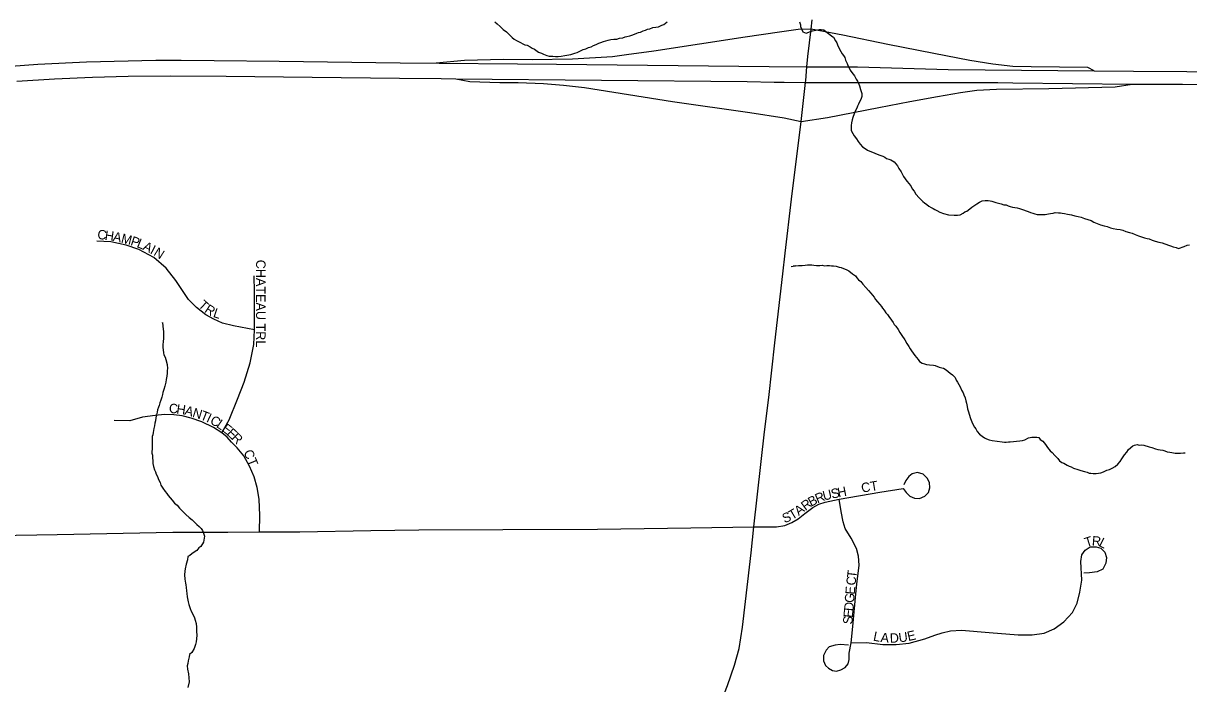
# Model space of a CAD drawing. Extents: x -10.1 to 68, y -9.5 to 29.2.
# Drawn here: x 4.36 to 5.531, y 18.755 to 19.418 of the extents above; entities that cross this region are included whole.
import ezdxf

# ---------------------------------------------------------------- set-up
doc = ezdxf.new("R2010")
doc.units = 0
for name, color, linetype in [('GM_X_Interchange_Ramps', 7, 'Continuous'), ('GM_X_Minor_River', 7, 'Continuous'), ('GM_X_Township_Road', 7, 'Continuous'), ('GM_X_Township_Subdivision', 7, 'Continuous'), ('GM_X_Township_Subdivision_Text', 7, 'Continuous'), ('GM_X_US_Route', 7, 'Continuous'), ('SH_Data', 7, 'Continuous')]:
    doc.layers.add(name, color=color, linetype=linetype)

msp = doc.modelspace()

# ---------------------------------------------------------------- linework, layer by layer
at = {"layer": 'GM_X_Interchange_Ramps'}
for points in [[(5.152, 19.4121), (5.1389, 19.4118), (5.1202, 19.4091), (5.0857, 19.4041), (4.9938, 19.3902), (4.9666, 19.3863), (4.9524, 19.3844), (4.9121, 19.3821), (4.8718, 19.3814), (4.8428, 19.3816), (4.8038, 19.3808), (4.7753, 19.3781)], [(5.4363, 19.3702), (5.4299, 19.3736), (5.3732, 19.3744), (5.3548, 19.3748), (5.3347, 19.3769), (5.3114, 19.3808), (5.2751, 19.3877), (5.2289, 19.3969), (5.1837, 19.4061), (5.152, 19.4121)], [(4.795, 19.3624), (4.8092, 19.3596), (4.8392, 19.3587), (4.8576, 19.3586), (4.8831, 19.3577), (4.9033, 19.3559), (4.9241, 19.3535), (4.9391, 19.3514), (5.0126, 19.3394), (5.0904, 19.3285), (5.1249, 19.3231), (5.1418, 19.3195)], [(5.1418, 19.3195), (5.1683, 19.3235), (5.2199, 19.3334), (5.251, 19.3395), (5.2791, 19.3447), (5.3019, 19.3487), (5.3183, 19.351), (5.3383, 19.3519), (5.3908, 19.3526), (5.4576, 19.3542), (5.4747, 19.3568)]]:
    msp.add_lwpolyline(points, dxfattribs=at)
at = {"layer": 'GM_X_Minor_River'}
for points in [[(4.8342, 19.4194), (4.8365, 19.4175), (4.8396, 19.415), (4.8427, 19.412), (4.8458, 19.4094), (4.8485, 19.4068), (4.8516, 19.4038), (4.8536, 19.4023), (4.8559, 19.4009), (4.8578, 19.3998), (4.8601, 19.3987), (4.8624, 19.3976), (4.8644, 19.3965), (4.8666, 19.3962), (4.8697, 19.3943), (4.8716, 19.3932), (4.874, 19.3921), (4.8782, 19.3892), (4.8809, 19.3881), (4.8832, 19.387), (4.8863, 19.3859), (4.8886, 19.3852), (4.8924, 19.3849), (4.895, 19.3846), (4.8977, 19.3847), (4.9007, 19.3851), (4.9045, 19.3856), (4.9106, 19.3869), (4.9125, 19.3873), (4.9144, 19.3881), (4.917, 19.3889), (4.9196, 19.3901), (4.923, 19.3917), (4.9257, 19.3925), (4.9283, 19.3937), (4.931, 19.3945), (4.9332, 19.3957), (4.9359, 19.3969), (4.9385, 19.3981), (4.9408, 19.3989), (4.9434, 19.3997), (4.9457, 19.4005), (4.9479, 19.401), (4.9506, 19.4018), (4.9536, 19.4022), (4.9567, 19.4023), (4.9593, 19.4031), (4.9627, 19.4036), (4.965, 19.4044), (4.9669, 19.4048), (4.9699, 19.4056), (4.9729, 19.4065), (4.9767, 19.4081), (4.9786, 19.4089), (4.9805, 19.4093), (4.9831, 19.4105), (4.9854, 19.4113), (4.9876, 19.4121), (4.9899, 19.4125), (4.9929, 19.4137), (4.996, 19.4142), (4.9986, 19.4146), (5.002, 19.4162), (5.0039, 19.417), (5.0073, 19.4194)], [(5.1404, 19.4196), (5.1412, 19.4166), (5.1413, 19.4147), (5.1425, 19.412), (5.1437, 19.4094), (5.1471, 19.4083), (5.1513, 19.4099), (5.1535, 19.4104), (5.16, 19.4117), (5.1619, 19.4117), (5.1646, 19.4114), (5.1669, 19.4099), (5.1707, 19.4069), (5.1727, 19.4051), (5.1746, 19.404), (5.1766, 19.4006), (5.1778, 19.3984), (5.1786, 19.3965), (5.1798, 19.3935), (5.1818, 19.3897), (5.1833, 19.3875), (5.1845, 19.3856), (5.1857, 19.3837), (5.1865, 19.3811), (5.1881, 19.3777), (5.1889, 19.3758), (5.1901, 19.3735), (5.1913, 19.3709), (5.1929, 19.3687), (5.1956, 19.3653), (5.1972, 19.3619), (5.1984, 19.36), (5.1999, 19.357), (5.2007, 19.3552), (5.2016, 19.3517), (5.2024, 19.3495), (5.2028, 19.3476), (5.2029, 19.3446), (5.2022, 19.3426), (5.1996, 19.3369), (5.1985, 19.335), (5.1978, 19.3327), (5.1967, 19.3304), (5.1953, 19.3273), (5.1938, 19.3235), (5.1931, 19.3212), (5.1924, 19.3181), (5.1921, 19.3154), (5.1921, 19.3128), (5.1922, 19.3105), (5.1938, 19.3075), (5.1953, 19.3049), (5.1977, 19.3019), (5.1993, 19.2993), (5.2012, 19.2966), (5.2036, 19.294), (5.2063, 19.2922), (5.2086, 19.2907), (5.2109, 19.2896), (5.2136, 19.2885)], [(5.2136, 19.2885), (5.2159, 19.2878), (5.2182, 19.2867), (5.2209, 19.2857), (5.2239, 19.2846), (5.2259, 19.2835), (5.2278, 19.2824), (5.2301, 19.2817), (5.232, 19.281), (5.2355, 19.2788), (5.2386, 19.275), (5.2402, 19.2724), (5.2425, 19.269), (5.2449, 19.2641), (5.248, 19.2596), (5.2504, 19.2567), (5.2524, 19.254), (5.2535, 19.2518), (5.2555, 19.2496), (5.2571, 19.2465), (5.2606, 19.2428), (5.2621, 19.241), (5.2641, 19.2391), (5.266, 19.2376), (5.2683, 19.2361), (5.2703, 19.2343), (5.2726, 19.2332), (5.2745, 19.2321), (5.2764, 19.231), (5.2784, 19.2299), (5.2814, 19.2285), (5.2849, 19.227), (5.2899, 19.2256), (5.2956, 19.2253), (5.299, 19.2254), (5.3016, 19.2258), (5.3047, 19.2274), (5.3065, 19.2286), (5.3084, 19.2294), (5.3114, 19.2318), (5.3133, 19.2333), (5.3155, 19.2349), (5.3185, 19.2369), (5.3212, 19.2384), (5.3238, 19.2396), (5.3268, 19.2401), (5.3299, 19.2401), (5.3318, 19.2398), (5.3337, 19.2395), (5.3356, 19.2387), (5.3375, 19.238), (5.3402, 19.2373), (5.3429, 19.2366), (5.3456, 19.2359), (5.3478, 19.2356), (5.3501, 19.2349), (5.3521, 19.2342), (5.3544, 19.2335), (5.3566, 19.2331), (5.3589, 19.2328), (5.3612, 19.2321), (5.3635, 19.2314), (5.37, 19.2289), (5.3723, 19.2281), (5.3746, 19.2274), (5.3769, 19.2267), (5.3792, 19.226), (5.3819, 19.2261), (5.3846, 19.2261), (5.3872, 19.2262), (5.3906, 19.2266), (5.3925, 19.2271), (5.3952, 19.2275), (5.3971, 19.2279), (5.4005, 19.2276), (5.4024, 19.2277), (5.4043, 19.2273), (5.4066, 19.227), (5.4097, 19.2263), (5.4135, 19.2256), (5.4169, 19.2246), (5.4204, 19.2239), (5.4234, 19.2232), (5.4265, 19.2221), (5.4299, 19.221), (5.4334, 19.22), (5.4361, 19.2185), (5.4395, 19.2171), (5.4426, 19.2156), (5.4464, 19.2146), (5.4495, 19.2139), (5.4526, 19.2128), (5.4556, 19.2121), (5.4591, 19.2114), (5.4625, 19.2111), (5.4652, 19.2104), (5.4682, 19.2089), (5.4717, 19.2079), (5.4747, 19.2072), (5.4774, 19.2061), (5.4809, 19.2047)], [(5.4809, 19.2047), (5.4839, 19.2036), (5.487, 19.2025), (5.4897, 19.2018), (5.4916, 19.2015), (5.4947, 19.2004), (5.4977, 19.1993), (5.5012, 19.1983), (5.5046, 19.1976), (5.5111, 19.1954), (5.513, 19.1947), (5.5157, 19.1936), (5.5188, 19.1929), (5.5211, 19.1919), (5.5268, 19.1939), (5.5298, 19.1951), (5.5321, 19.1955)], [(5.1319, 19.1739), (5.1361, 19.1744), (5.1338, 19.1743), (5.1361, 19.1744), (5.1392, 19.1748), (5.1411, 19.1749), (5.143, 19.1749), (5.146, 19.1753), (5.1483, 19.1754), (5.1506, 19.1754), (5.1528, 19.1755), (5.1547, 19.1752), (5.1574, 19.1748), (5.1608, 19.1749), (5.1631, 19.175), (5.1654, 19.1746), (5.1677, 19.1747), (5.1704, 19.1747), (5.1726, 19.1744), (5.1745, 19.1744), (5.1772, 19.1741), (5.1803, 19.1731), (5.1822, 19.1727), (5.1879, 19.1706), (5.1899, 19.1695), (5.1934, 19.1665), (5.1964, 19.1643), (5.198, 19.1624), (5.1996, 19.1605), (5.2019, 19.1587), (5.2038, 19.1561), (5.207, 19.1527), (5.2097, 19.1497), (5.212, 19.1471), (5.2136, 19.1449), (5.2152, 19.143), (5.2167, 19.1408), (5.2187, 19.1382), (5.221, 19.1356), (5.2226, 19.1337), (5.2238, 19.1318), (5.2253, 19.1299), (5.2269, 19.1273), (5.2288, 19.1255), (5.23, 19.1236), (5.2328, 19.1198), (5.2343, 19.1176), (5.2355, 19.1157), (5.2371, 19.1139), (5.2394, 19.1105), (5.241, 19.1075), (5.243, 19.1045), (5.2461, 19.1), (5.2481, 19.0966), (5.2501, 19.0936), (5.2516, 19.091), (5.2528, 19.0891), (5.2544, 19.0869), (5.2563, 19.0843), (5.2579, 19.0824), (5.2595, 19.0805), (5.261, 19.0783), (5.2637, 19.0768), (5.266, 19.0761), (5.2679, 19.0754), (5.271, 19.0751), (5.2748, 19.0748), (5.2767, 19.0744), (5.2806, 19.0726), (5.2832, 19.0719), (5.2851, 19.0716), (5.2878, 19.0701), (5.2917, 19.0668), (5.294, 19.0649), (5.2968, 19.0623), (5.2976, 19.0597), (5.2991, 19.0578), (5.3003, 19.0552), (5.3019, 19.0522), (5.3031, 19.0495), (5.3047, 19.0469), (5.3055, 19.045), (5.3067, 19.042), (5.3075, 19.039), (5.308, 19.0364), (5.3088, 19.0333), (5.3092, 19.0307), (5.31, 19.0277), (5.3109, 19.0254), (5.3121, 19.0212), (5.3133, 19.0178), (5.3145, 19.0156), (5.3161, 19.0126), (5.3173, 19.0107), (5.3188, 19.0081), (5.3212, 19.0055), (5.3239, 19.0033), (5.3262, 19.0018), (5.3281, 19.0007), (5.3308, 18.9996), (5.3339, 18.9989)], [(4.5002, 19.1172), (4.5002, 19.1176), (4.5006, 19.1138), (4.5011, 19.1081), (4.5012, 19.1043), (4.5013, 19.1017), (4.501, 19.0983), (4.5006, 19.0956), (4.5007, 19.0929), (4.5012, 19.0872), (4.5016, 19.085), (4.5028, 19.0827), (4.5036, 19.0805), (4.5049, 19.0755), (4.5053, 19.0714), (4.505, 19.0695), (4.505, 19.0668), (4.5047, 19.0638), (4.504, 19.0603), (4.5037, 19.0577), (4.5027, 19.0535), (4.5016, 19.0504), (4.5005, 19.0473), (4.5002, 19.0454), (4.4995, 19.0427), (4.4984, 19.0397), (4.4977, 19.037), (4.497, 19.0343), (4.4963, 19.0324), (4.4952, 19.0297), (4.4949, 19.0274), (4.4941, 19.0248), (4.4935, 19.0217), (4.4931, 19.0187), (4.4924, 19.0164), (4.4921, 19.0137), (4.4914, 19.011), (4.4911, 19.0091), (4.4907, 19.0072), (4.4904, 19.0049), (4.49, 19.003), (4.4897, 18.9996), (4.4898, 18.9977), (4.4898, 18.9958), (4.4899, 18.9927), (4.4899, 18.9901), (4.4896, 18.9882), (4.4896, 18.9863), (4.4901, 18.9844), (4.4906, 18.976), (4.4911, 18.973), (4.4923, 18.9696), (4.4931, 18.9677), (4.4939, 18.9651), (4.4951, 18.9628), (4.4959, 18.961), (4.4967, 18.9591), (4.4979, 18.9568), (4.4987, 18.9542), (4.5007, 18.9512), (4.503, 18.9478), (4.5046, 18.9459), (4.5061, 18.9437), (4.5081, 18.9415), (4.51, 18.9392), (4.5124, 18.9362), (4.5151, 18.934), (4.5174, 18.931), (4.5206, 18.9277), (4.5237, 18.9247), (4.5272, 18.9217), (4.5299, 18.9195), (4.5318, 18.9177), (4.5349, 18.9147), (4.5372, 18.9128), (4.5392, 18.9106), (4.5404, 18.9087), (4.5416, 18.9061), (4.5424, 18.9031), (4.5414, 18.897), (4.5388, 18.8927), (4.5369, 18.8912), (4.5347, 18.8885), (4.5321, 18.8869), (4.5298, 18.8853), (4.5276, 18.8837), (4.5257, 18.8826), (4.5254, 18.8791), (4.524, 18.8749), (4.5229, 18.87), (4.5226, 18.8677), (4.5223, 18.8642), (4.5228, 18.8597), (4.5232, 18.8559), (4.5237, 18.854), (4.5241, 18.8514), (4.5245, 18.8479), (4.5246, 18.8453), (4.5251, 18.8419), (4.5259, 18.837), (4.5267, 18.8343)], [(5.3339, 18.9989), (5.3438, 18.9976), (5.3461, 18.9973), (5.348, 18.9973), (5.3502, 18.9977), (5.3521, 18.9978), (5.3552, 18.9982), (5.3582, 18.9983), (5.3616, 18.9988), (5.3643, 18.9992), (5.3666, 18.9996), (5.3703, 19.0016), (5.3737, 19.0024), (5.3756, 19.0025), (5.3787, 19.0025), (5.3806, 19.0022), (5.3822, 19), (5.3848, 18.9985), (5.3876, 18.9951), (5.3895, 18.9921), (5.3923, 18.9888), (5.3942, 18.9869), (5.3969, 18.9839), (5.3997, 18.981), (5.4016, 18.9787), (5.4039, 18.9769), (5.4059, 18.9762), (5.4093, 18.9743), (5.4113, 18.9732), (5.4132, 18.9725), (5.4155, 18.9714), (5.4201, 18.97), (5.4228, 18.9689), (5.4266, 18.9679), (5.4293, 18.9672), (5.4312, 18.9664), (5.4331, 18.9661), (5.4354, 18.9658), (5.4384, 18.9658), (5.4407, 18.9663), (5.443, 18.9667), (5.4456, 18.9675), (5.449, 18.9691), (5.4516, 18.9699), (5.4543, 18.9711), (5.4573, 18.9731), (5.4603, 18.9754), (5.4625, 18.9781), (5.464, 18.9805), (5.4654, 18.9828), (5.4669, 18.9847), (5.4691, 18.9874), (5.471, 18.9901), (5.4751, 18.9936), (5.477, 18.9944), (5.4796, 18.9949), (5.4816, 18.9945), (5.4842, 18.9946), (5.4861, 18.9942), (5.4915, 18.9928), (5.4942, 18.9921), (5.498, 18.9907), (5.5003, 18.99), (5.5026, 18.9897), (5.5052, 18.9893), (5.5075, 18.9886), (5.5098, 18.9875), (5.5125, 18.9872), (5.5144, 18.9869), (5.5179, 18.9862), (5.5198, 18.9862), (5.5232, 18.9863), (5.5262, 18.9867), (5.5277, 18.9868)], [(4.5267, 18.8343), (4.528, 18.8302), (4.5292, 18.8275), (4.5307, 18.8245), (4.5323, 18.8211), (4.5332, 18.8185), (4.534, 18.8151), (4.5344, 18.8117), (4.5345, 18.8098), (4.5345, 18.8075), (4.5346, 18.8033), (4.534, 18.7968), (4.5333, 18.7942), (4.5322, 18.7903), (4.5297, 18.7861), (4.5274, 18.7842), (4.5271, 18.7819), (4.526, 18.7777), (4.5257, 18.775), (4.525, 18.7727), (4.5255, 18.7693), (4.5263, 18.7648), (4.5272, 18.7568), (4.5258, 18.7511)]]:
    msp.add_lwpolyline(points, dxfattribs=at)
at = {"layer": 'GM_X_Township_Road'}
msp.add_lwpolyline([(4.2911, 18.9031), (4.3945, 18.9047), (4.5107, 18.907), (4.5408, 18.907), (4.5658, 18.907), (4.5976, 18.9074), (4.6383, 18.9074), (4.7095, 18.9088), (4.7577, 18.9092), (4.8421, 18.9097), (4.9373, 18.9101), (5.0312, 18.9115), (5.0945, 18.9125)], dxfattribs=at)
at = {"layer": 'GM_X_Township_Subdivision'}
for points in [[(4.5926, 19.1101), (4.5715, 19.1141), (4.5606, 19.117), (4.5519, 19.1209), (4.5438, 19.1251), (4.5345, 19.1326), (4.5264, 19.1407), (4.5138, 19.1598), (4.5039, 19.172), (4.4915, 19.1828), (4.4764, 19.1909), (4.4638, 19.1952), (4.4483, 19.1985), (4.4343, 19.1994)], [(4.5597, 19.0067), (4.5672, 19.0198), (4.5757, 19.0405), (4.5823, 19.0578), (4.5883, 19.077), (4.5919, 19.0954), (4.5926, 19.1101), (4.5926, 19.1483), (4.5922, 19.1645)], [(4.5976, 18.9074), (4.598, 18.9236), (4.5973, 18.9401), (4.5955, 18.9518), (4.5922, 18.9624), (4.5877, 18.9734), (4.582, 18.9837), (4.5753, 18.9916), (4.5697, 18.9975), (4.5651, 19.0024), (4.5597, 19.0067), (4.5514, 19.0121), (4.5397, 19.0177), (4.5291, 19.0216), (4.5199, 19.0238), (4.5116, 19.0247), (4.5021, 19.0252), (4.4929, 19.0243), (4.4803, 19.0225), (4.4674, 19.0189), (4.4517, 19.0191)], [(5.0945, 18.9125), (5.1093, 18.9123), (5.1173, 18.9125), (5.1254, 18.9138), (5.1325, 18.9166), (5.139, 18.9205), (5.1458, 18.9256), (5.1536, 18.9316), (5.1598, 18.9351), (5.1662, 18.937), (5.1802, 18.94), (5.221, 18.9471), (5.2446, 18.951), (5.2474, 18.9469), (5.2511, 18.943), (5.2558, 18.9411), (5.2609, 18.9407), (5.2661, 18.943), (5.27, 18.9469), (5.2713, 18.9516), (5.2708, 18.957), (5.2687, 18.9613), (5.2644, 18.9651), (5.259, 18.9669), (5.2536, 18.9656), (5.25, 18.9628), (5.247, 18.9589), (5.2451, 18.9546)], [(5.1896, 18.7935), (5.181, 18.794), (5.1761, 18.7935), (5.1701, 18.7918), (5.1671, 18.7886), (5.1643, 18.7832), (5.1645, 18.7779), (5.1664, 18.7731), (5.1695, 18.7703), (5.1735, 18.7682), (5.1776, 18.7675), (5.1819, 18.7688), (5.1862, 18.771), (5.1892, 18.7746), (5.1903, 18.7791), (5.1903, 18.7856), (5.1922, 18.7957), (5.1939, 18.8124), (5.1969, 18.8451), (5.198, 18.8549), (5.2002, 18.8739), (5.1997, 18.8829), (5.1974, 18.8906), (5.1922, 18.9009), (5.1862, 18.9106), (5.1841, 18.9172), (5.1823, 18.9276), (5.1802, 18.94)], [(5.1922, 18.7957), (5.2075, 18.7961), (5.224, 18.794), (5.2373, 18.7942), (5.2506, 18.7955), (5.2663, 18.8), (5.2764, 18.8036), (5.2837, 18.8058), (5.2919, 18.8079), (5.303, 18.8084), (5.3308, 18.8062), (5.36, 18.8038), (5.3741, 18.8038), (5.3862, 18.8056), (5.396, 18.8099), (5.4059, 18.8169), (5.4145, 18.8264), (5.4192, 18.8358), (5.422, 18.8466), (5.424, 18.8588), (5.4231, 18.8775), (5.424, 18.8842), (5.4272, 18.8889), (5.4323, 18.8921), (5.4384, 18.8923), (5.4431, 18.8908), (5.4472, 18.887), (5.4489, 18.8816), (5.4482, 18.876), (5.445, 18.8698), (5.4394, 18.8672), (5.4317, 18.8663), (5.4259, 18.8657)]]:
    msp.add_lwpolyline(points, dxfattribs=at)
at = {"layer": 'GM_X_US_Route'}
for points in [[(4.3119, 19.3724), (4.3751, 19.3769), (4.424, 19.3795), (4.4934, 19.3812), (4.5189, 19.381), (4.5522, 19.3808), (4.6173, 19.3802), (4.7391, 19.3784), (4.8962, 19.3769), (5.1099, 19.3748), (5.1478, 19.3745), (5.1986, 19.3742), (5.2897, 19.3718), (5.3268, 19.3712), (5.4363, 19.3702), (5.476, 19.3699), (5.5294, 19.3695), (5.6863, 19.3671)], [(4.3539, 19.36), (4.3916, 19.3622), (4.43, 19.3641), (4.4658, 19.3649), (4.5086, 19.3654), (4.5642, 19.3649), (4.6505, 19.3639), (4.7384, 19.363), (4.7804, 19.3626), (4.795, 19.3624), (5.0876, 19.3596), (5.1148, 19.3589), (5.1249, 19.3588)], [(5.1249, 19.3588), (5.1449, 19.3586)], [(5.1449, 19.3586), (5.1463, 19.3586), (5.3397, 19.3585), (5.3548, 19.3583)], [(5.3548, 19.3583), (5.4747, 19.3568), (5.5251, 19.3568), (5.6201, 19.3557), (5.7107, 19.3549), (5.8342, 19.3532), (5.8437, 19.3531)]]:
    msp.add_lwpolyline(points, dxfattribs=at)
at = {"layer": 'SH_Data'}
for points in [[(5.1465, 19.3606), (5.1478, 19.3745), (5.1488, 19.3847), (5.152, 19.4121), (5.1531, 19.4217)], [(5.1418, 19.3195), (5.1418, 19.3195), (5.1463, 19.3586), (5.1465, 19.3606)], [(5.1259, 19.1873), (5.1321, 19.2413), (5.1418, 19.3195)], [(5.0544, 18.7187), (5.0679, 18.7529), (5.0749, 18.7733), (5.0795, 18.7901), (5.0829, 18.8114), (5.0885, 18.8573), (5.0917, 18.8861), (5.0945, 18.9125), (5.1052, 19.0076), (5.1094, 19.0423), (5.1155, 19.0973), (5.1235, 19.1666), (5.1259, 19.1873)]]:
    msp.add_lwpolyline(points, dxfattribs=at)

# ---------------------------------------------------------------- texts
at = {"layer": 'GM_X_Township_Subdivision_Text'}
for s, rotation, p in [('C', 353.1852, (4.4344, 19.2016)), ('H', 351.9533, (4.4418, 19.2007)), ('A', 348.5143, (4.4499, 19.1996)), ('M', 345.7385, (4.458, 19.1979)), ('P', 341.5737, (4.4675, 19.1955)), ('L', 337.9602, (4.4737, 19.1935)), ('A', 334.08, (4.4797, 19.191)), ('I', 332.3208, (4.4871, 19.1874)), ('N', 327.7166, (4.4906, 19.1856)), ('CHATEAU TRL', 270, (4.5943, 19.1806)), ('T', 317.5315, (4.5355, 19.134)), ('R', 327.3703, (4.5418, 19.1285)), ('L', 341.8924, (4.5505, 19.1233)), ('C', 357.9355, (4.5066, 19.0266)), ('H', 351.6195, (4.5138, 19.0263)), ('A', 344.3788, (4.5218, 19.0252)), ('N', 342.8298, (4.5297, 19.023)), ('T', 338.782, (4.5375, 19.0206)), ('I', 334.9408, (4.5436, 19.0182)), ('C', 331.0775, (4.5472, 19.0165)), ('L', 325.787, (4.5536, 19.013)), ('E', 322.1466, (4.559, 19.0094)), ('E', 317.0682, (4.5641, 19.0054)), ('R', 315.2405, (4.5689, 19.0009)), ('CT', 292.4212, (4.5815, 18.9876)), ('CT', 9.4702, (5.2031, 18.9466)), ('R', 22.7712, (5.1583, 18.9358)), ('U', 13.5485, (5.1648, 18.9386)), ('S', 11.7226, (5.1729, 18.9406)), ('H', 11.6399, (5.1794, 18.9419)), ('R', 36.4327, (5.1462, 18.9282)), ('B', 27.9339, (5.1519, 18.9324)), ('S', 21.4259, (5.1251, 18.9159)), ('T', 30.6187, (5.1328, 18.9191)), ('A', 37.2186, (5.1395, 18.9232)), ('T', 17.6572, (5.4284, 18.8918)), ('R', 355.5026, (5.4338, 18.8937)), ('L', 333.3372, (5.4404, 18.8934)), ('T', 83.3189, (5.1973, 18.8605)), ('E', 85.3418, (5.1957, 18.844)), ('C', 83.9897, (5.1965, 18.8531)), ('G', 85.2962, (5.195, 18.8357)), ('E', 85.3027, (5.1938, 18.8208)), ('D', 85.318, (5.1944, 18.8274)), ('S', 85.3226, (5.1933, 18.8141)), ('L', 348.3365, (5.2138, 18.7982)), ('A', 353.9888, (5.2214, 18.7967)), ('D', 2.3372, (5.2312, 18.7958)), ('U', 7.6896, (5.2405, 18.7962)), ('E', 12.9969, (5.2497, 18.7975))]:
    msp.add_text(s, height=0.00947, rotation=rotation, dxfattribs=at).set_placement(p)

doc.saveas('drawing.dxf')
